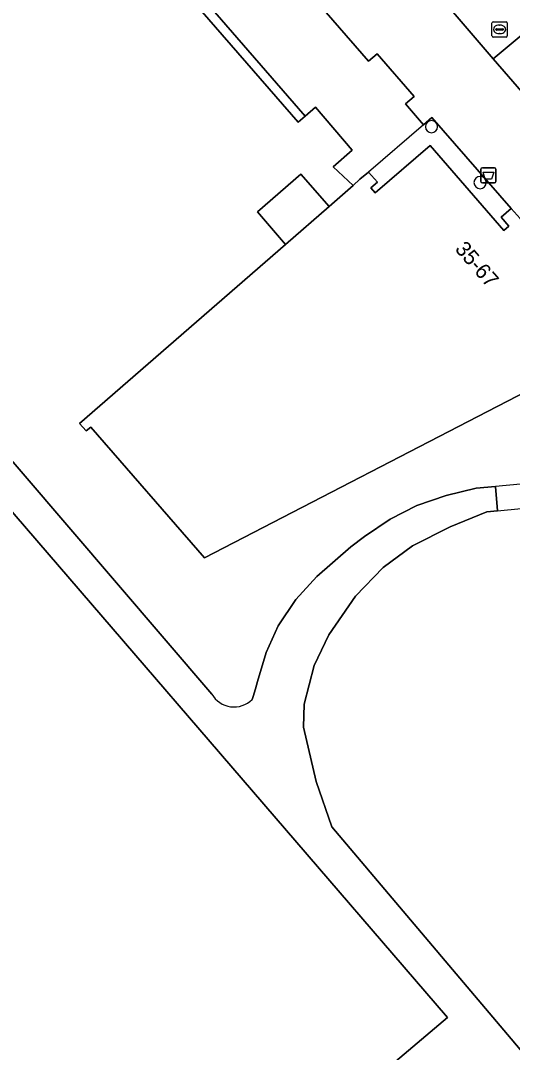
# Model space of a CAD drawing. Extents: x 155887 to 156869, y 383880 to 384678.
# Drawn here: x 156276.5 to 156308.7, y 383981.9 to 384049.5 of the extents above; entities that cross this region are included whole.
import ezdxf

# ---------------------------------------------------------------- set-up
doc = ezdxf.new("R2010")
doc.units = 0
for name, color, linetype in [('IMGEO_Afvalbak', 7, 'Continuous'), ('IMGEO_Berm_groen', 7, 'Continuous'), ('IMGEO_Dek', 7, 'Continuous'), ('IMGEO_Erf', 7, 'Continuous'), ('IMGEO_Muur', 7, 'Continuous'), ('IMGEO_Pand', 7, 'Continuous'), ('IMGEO_Pand_nummerreeks', 7, 'Continuous'), ('IMGEO_Pand_overbouw', 7, 'Continuous'), ('IMGEO_Rioolput', 7, 'Continuous'), ('IMGEO_Voetpad_gesloten', 7, 'Continuous'), ('IMGEO_Voetpad_op_trap', 7, 'Continuous'), ('IMGEO_Voetpad_open', 7, 'Continuous')]:
    doc.layers.add(name, color=color, linetype=linetype)

msp = doc.modelspace()

# ---------------------------------------------------------------- linework, layer by layer
at = {"layer": 'IMGEO_Afvalbak'}
for p, q in [((156306.776, 384039.847), (156307.566, 384039.847)), ((156307.566, 384039.847), (156306.776, 384039.847)), ((156306.676, 384038.947), (156306.676, 384039.747)), ((156306.676, 384039.747), (156306.676, 384038.947)), ((156307.666, 384039.747), (156307.666, 384038.947)), ((156307.666, 384038.947), (156307.666, 384039.747)), ((156307.566, 384038.847), (156306.776, 384038.847)), ((156306.776, 384038.847), (156307.566, 384038.847))]:
    msp.add_line(p, q, dxfattribs=at)
msp.add_lwpolyline([(156306.819, 384039.561), (156307.523, 384039.561), (156307.374, 384039.091), (156306.968, 384039.091), (156306.819, 384039.561)], dxfattribs=at)
for centre, start, end in [((156306.776, 384039.747), 90, 180), ((156306.776, 384039.747), 90, 180), ((156307.566, 384039.747), 0, 90), ((156307.566, 384039.747), 360, 90), ((156306.776, 384038.947), 180, 270), ((156306.776, 384038.947), 180, 270), ((156307.566, 384038.947), 270, 0), ((156307.566, 384038.947), 270, 0)]:
    msp.add_arc(centre, 0.1, start, end, dxfattribs=at)
at = {"layer": 'IMGEO_Berm_groen'}
msp.add_lwpolyline([(156309.711, 384048.832), (156307.48, 384046.967), (156334.824, 384015.476), (156337.029, 384017.397)], close=True, dxfattribs=at)
at = {"layer": 'IMGEO_Dek'}
msp.add_lwpolyline([(156307.645, 384018.989), (156307.772, 384017.39), (156315.941, 384018.196), (156316.839, 384018.284), (156323.542, 384018.946), (156325.9, 384019.178), (156325.757, 384020.632), (156322.341, 384020.322), (156315.596, 384019.71), (156314.665, 384019.626)], close=True, dxfattribs=at)
at = {"layer": 'IMGEO_Erf'}
for points in [[(156309.681, 384025.215), (156288.569, 384014.304), (156281.129, 384022.863), (156280.825, 384022.622), (156280.395, 384023.106), (156293.888, 384034.824), (156292.042, 384036.949), (156294.891, 384039.423), (156296.736, 384037.298), (156298.319, 384038.673), (156296.994, 384039.913), (156298.259, 384041.003), (156295.842, 384043.805), (156295.178, 384043.225), (156294.72, 384042.825), (156278.03, 384061.999)], [(156285.936, 384053.867), (156295.178, 384043.225), (156295.842, 384043.805), (156298.259, 384041.003), (156296.994, 384039.913), (156298.319, 384038.673), (156298.76, 384039.086), (156299.323, 384039.554), (156299.905, 384038.897), (156299.472, 384038.525), (156299.753, 384038.199), (156303.358, 384041.301), (156308.189, 384035.743), (156308.515, 384036.024), (156308.006, 384036.615), (156308.666, 384037.183), (156303.465, 384043.137), (156302.926, 384042.662), (156301.74, 384044.032), (156302.314, 384044.516), (156299.889, 384047.289), (156299.309, 384046.811), (156292.746, 384054.384)], [(156257.832, 384041.816), (156289.058, 384005.394)], [(156207.88, 383988.6), (156234.749, 383984.953), (156264.705, 383981.143), (156294.664, 383977.039), (156295.833, 383976.891), (156304.5, 383984.231), (156256.372, 384040.069)], [(156302.473, 384017.748), (156304.399, 384018.396), (156306.365, 384018.873), (156307.645, 384018.989), (156307.772, 384017.39), (156307.069, 384017.32), (156304.657, 384016.349), (156302.204, 384015.091), (156300.277, 384013.673), (156298.459, 384011.812), (156296.718, 384009.276), (156295.763, 384007.263), (156295.11, 384004.736), (156295.063, 384003.225), (156295.882, 383999.681), (156296.917, 383996.704), (156315.845, 383974.354)], [(156291.7, 384005.036), (156291.775, 384005.235), (156291.922, 384005.742), (156292.058, 384006.21), (156292.611, 384008.116), (156293.411, 384009.855), (156294.569, 384011.595), (156295.929, 384013.086), (156298.167, 384015.027), (156299.058, 384015.714), (156300.729, 384016.85), (156302.473, 384017.748)]]:
    msp.add_lwpolyline(points, dxfattribs=at)
for centre, radius, start, end in [((156303.445, 384042.532), 0.4, 0, 180), ((156303.445, 384042.532), 0.4, 180, 0), ((156306.626, 384038.872), 0.4, 0, 180), ((156306.626, 384038.872), 0.4, 180, 360), ((156290.517, 384006.236), 1.685, 209.97052, 314.59593)]:
    msp.add_arc(centre, radius, start, end, dxfattribs=at)
at = {"layer": 'IMGEO_Muur'}
msp.add_lwpolyline([(156285.936, 384053.867), (156284.731, 384055.254), (156279.098, 384061.741), (156284.274, 384064.281), (156283.684, 384064.959), (156278.03, 384061.999), (156294.72, 384042.825), (156295.178, 384043.225)], close=True, dxfattribs=at)
for points in [[(156295.178, 384043.225), (156295.842, 384043.805)], [(156295.842, 384043.805), (156298.259, 384041.003)], [(156298.259, 384041.003), (156296.994, 384039.913), (156298.319, 384038.673)]]:
    msp.add_lwpolyline(points, dxfattribs=at)
at = {"layer": 'IMGEO_Pand'}
for points in [[(156309.249, 384036.526), (156308.666, 384037.183), (156308.006, 384036.615), (156308.515, 384036.024), (156308.189, 384035.743), (156303.358, 384041.301), (156299.753, 384038.199), (156299.472, 384038.525), (156299.905, 384038.897), (156299.323, 384039.554), (156298.76, 384039.086), (156298.319, 384038.673), (156296.736, 384037.298), (156293.888, 384034.824), (156280.395, 384023.106), (156280.825, 384022.622), (156281.129, 384022.863), (156288.569, 384014.304), (156309.681, 384025.215), (156315.525, 384028.392), (156316.047, 384027.689), (156316.55, 384027.123), (156317.037, 384027.543)], [(156293.888, 384034.824), (156296.736, 384037.298), (156294.891, 384039.423), (156292.042, 384036.949)]]:
    msp.add_lwpolyline(points, close=True, dxfattribs=at)
for centre, start, end in [((156303.445, 384042.532), 0, 180), ((156303.445, 384042.532), 180, 0), ((156306.626, 384038.872), 0, 180), ((156306.626, 384038.872), 180, 360)]:
    msp.add_arc(centre, 0.4, start, end, dxfattribs=at)
at = {"layer": 'IMGEO_Pand_overbouw'}
msp.add_lwpolyline([(156308.189, 384035.743), (156308.515, 384036.024), (156308.006, 384036.615), (156308.666, 384037.183), (156303.465, 384043.137), (156302.926, 384042.662), (156299.323, 384039.554), (156299.905, 384038.897), (156299.472, 384038.525), (156299.753, 384038.199), (156303.358, 384041.301)], close=True, dxfattribs=at)
at = {"layer": 'IMGEO_Rioolput'}
for p, q in [((156307.405, 384048.475), (156307.405, 384049.327)), ((156307.48, 384049.401), (156308.332, 384049.401)), ((156308.406, 384049.327), (156308.406, 384048.475)), ((156307.664, 384048.895), (156307.664, 384048.907)), ((156308.102, 384048.858), (156307.704, 384048.858)), ((156307.707, 384048.944), (156308.105, 384048.944)), ((156307.916, 384048.621), (156307.891, 384048.621)), ((156307.893, 384049.181), (156307.918, 384049.181)), ((156308.148, 384048.907), (156308.148, 384048.895)), ((156308.332, 384048.401), (156307.48, 384048.401))]:
    msp.add_line(p, q, dxfattribs=at)
for points in [[(156307.405, 384048.475), (156307.405, 384049.327)], [(156307.48, 384049.401), (156308.332, 384049.401)], [(156308.406, 384049.327), (156308.406, 384048.475)], [(156308.332, 384048.401), (156307.48, 384048.401)]]:
    msp.add_lwpolyline(points, dxfattribs=at)
for centre, radius, start, end in [((156307.482, 384049.325), 0.0765, 91.55205, 178.44795), ((156307.482, 384049.325), 0.0765, 91.55205, 178.44795), ((156308.33, 384049.325), 0.0765, 1.55205, 88.44795), ((156308.33, 384049.325), 0.0765, 1.55205, 88.44795), ((156307.704, 384048.904), 0.0403, 85.87752, 175.75265), ((156307.701, 384048.894), 0.0366, 178.93798, 274.71019), ((156308.105, 384048.901), 0.043, 264.86636, 352.45326), ((156308.109, 384048.906), 0.0386, 1.73085, 96.63898), ((156307.482, 384048.477), 0.0765, 181.55205, 268.44795), ((156307.482, 384048.477), 0.0765, 181.55205, 268.44795), ((156308.33, 384048.477), 0.0765, 271.55205, 358.44795), ((156308.33, 384048.477), 0.0765, 271.55205, 358.44795)]:
    msp.add_arc(centre, radius, start, end, dxfattribs=at)
for centre, major_axis, ratio, start_param, end_param in [((156307.892, 384048.901), (-0.387, 0.002), 0.722429, 4.712389, 7.853982), ((156307.917, 384048.901), (-0.39, 0.002), 0.717154, 1.570796, 4.712389)]:
    msp.add_ellipse(centre, major_axis=major_axis, ratio=ratio, start_param=start_param, end_param=end_param, dxfattribs=at)
at = {"layer": 'IMGEO_Voetpad_gesloten'}
for points in [[(156289.058, 384005.394), (156257.832, 384041.816)], [(156256.372, 384040.069), (156304.5, 383984.231), (156295.833, 383976.891), (156297.002, 383976.743), (156315.845, 383974.354), (156296.917, 383996.704), (156295.882, 383999.681), (156295.063, 384003.225), (156295.11, 384004.736), (156295.763, 384007.263), (156296.718, 384009.276), (156298.459, 384011.812), (156300.277, 384013.673), (156302.204, 384015.091), (156304.657, 384016.349), (156307.069, 384017.32)], [(156307.069, 384017.32), (156307.772, 384017.39), (156307.645, 384018.989), (156306.365, 384018.873), (156304.399, 384018.396), (156302.473, 384017.748), (156300.729, 384016.85), (156299.058, 384015.714), (156298.167, 384015.027), (156295.929, 384013.086), (156294.569, 384011.595), (156293.411, 384009.855), (156292.611, 384008.116), (156292.058, 384006.21), (156291.922, 384005.742), (156291.775, 384005.235), (156291.7, 384005.036)]]:
    msp.add_lwpolyline(points, dxfattribs=at)
msp.add_arc((156290.517, 384006.236), 1.685, 209.97052, 314.59593, dxfattribs=at)
at = {"layer": 'IMGEO_Voetpad_op_trap'}
msp.add_lwpolyline([(156307.645, 384018.989), (156307.772, 384017.39), (156315.941, 384018.196), (156316.839, 384018.284), (156323.542, 384018.946), (156325.9, 384019.178), (156325.757, 384020.632), (156322.341, 384020.322), (156315.596, 384019.71), (156314.665, 384019.626)], close=True, dxfattribs=at)
at = {"layer": 'IMGEO_Voetpad_open'}
msp.add_lwpolyline([(156313.707, 384052.278), (156310.356, 384056.143), (156306.981, 384053.222), (156306.425, 384052.676), (156304.211, 384050.794), (156307.48, 384046.967), (156309.711, 384048.832), (156310.33, 384049.351)], close=True, dxfattribs=at)
for points in [[(156292.746, 384054.384), (156299.309, 384046.811), (156299.889, 384047.289), (156302.314, 384044.516), (156301.74, 384044.032), (156302.926, 384042.662), (156303.465, 384043.137), (156308.666, 384037.183), (156309.249, 384036.526)], [(156338.584, 384011.11), (156334.824, 384015.476), (156307.48, 384046.967), (156304.211, 384050.794)]]:
    msp.add_lwpolyline(points, dxfattribs=at)

# ---------------------------------------------------------------- texts
at = {"layer": 'IMGEO_Pand_nummerreeks'}
msp.add_text('35-67', height=1, rotation=311.00065, dxfattribs=at).set_placement((156304.932, 384034.492))

doc.saveas('drawing.dxf')
